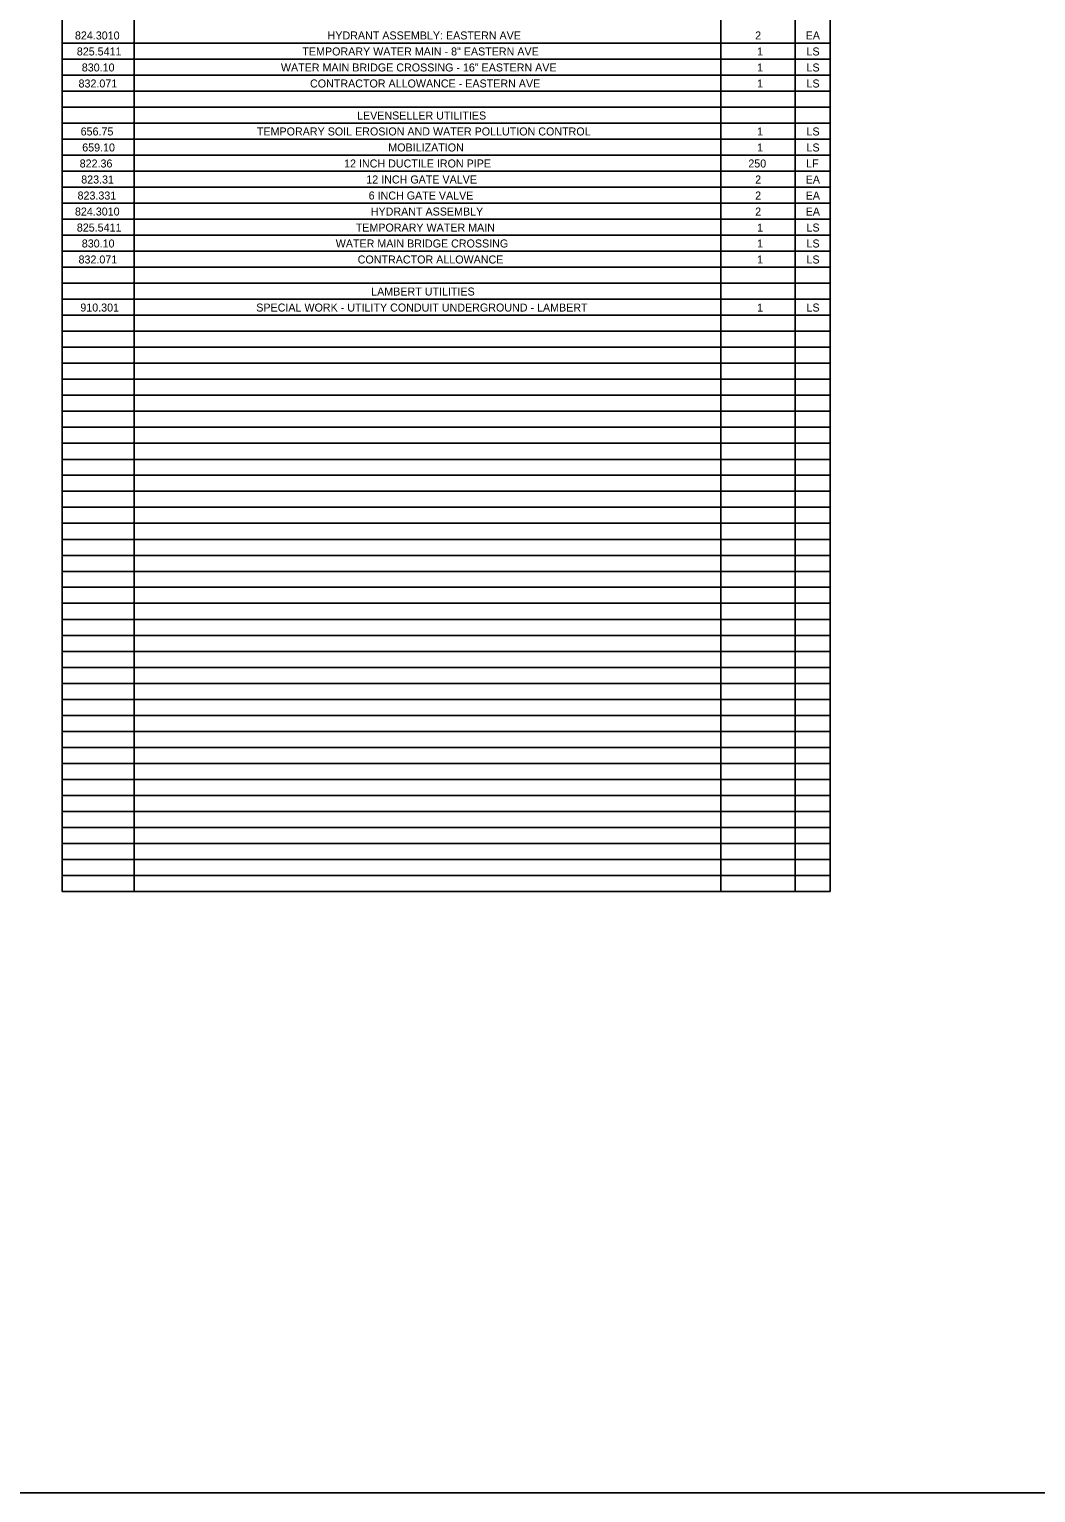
# Model space of a CAD drawing. Extents: x -18.7 to 5.6, y -2.7 to 5.1.
# Drawn here: x -5.226 to -3.989, y 1.503 to 3.303 of the extents above; entities that cross this region are included whole.
import ezdxf

# ---------------------------------------------------------------- set-up
doc = ezdxf.new("R2010")
doc.units = 0
for name, color, linetype in [('ANNOTATION', 7, 'Continuous'), ('BORDER', 7, 'Continuous'), ('Default', 7, 'Continuous')]:
    doc.layers.add(name, color=color, linetype=linetype)

msp = doc.modelspace()

# ---------------------------------------------------------------- linework, layer by layer
at = {"layer": 'BORDER'}
for p, q in [((-5.0975, 3.9551), (-5.0975, 2.2424)), ((-4.3761, 3.9551), (-4.3761, 2.2424)), ((-4.2848, 3.9551), (-4.2848, 2.2424)), ((-5.186, 3.2858), (-4.2418, 3.2858)), ((-5.186, 3.2661), (-4.2418, 3.2661)), ((-5.186, 3.2464), (-4.2418, 3.2464)), ((-5.186, 3.2267), (-4.2418, 3.2267)), ((-5.186, 3.207), (-4.2418, 3.207)), ((-5.186, 3.1873), (-4.2418, 3.1873)), ((-5.186, 3.1677), (-4.2418, 3.1677)), ((-5.186, 3.148), (-4.2418, 3.148)), ((-5.186, 3.1283), (-4.2418, 3.1283)), ((-5.186, 3.1086), (-4.2418, 3.1086)), ((-5.186, 3.0889), (-4.2418, 3.0889)), ((-5.186, 3.0692), (-4.2418, 3.0692)), ((-5.186, 3.0495), (-4.2418, 3.0495)), ((-5.186, 3.0299), (-4.2418, 3.0299)), ((-5.186, 3.0102), (-4.2418, 3.0102)), ((-5.186, 2.9905), (-4.2418, 2.9905)), ((-5.186, 2.9708), (-4.2418, 2.9708)), ((-5.186, 2.9511), (-4.2418, 2.9511)), ((-5.186, 2.9314), (-4.2418, 2.9314)), ((-5.186, 2.9117), (-4.2418, 2.9117)), ((-5.186, 2.8921), (-4.2418, 2.8921)), ((-5.186, 2.8724), (-4.2418, 2.8724)), ((-5.186, 2.8527), (-4.2418, 2.8527)), ((-5.186, 2.833), (-4.2418, 2.833)), ((-5.186, 2.8133), (-4.2418, 2.8133)), ((-5.186, 2.7936), (-4.2418, 2.7936)), ((-5.186, 2.7739), (-4.2418, 2.7739)), ((-5.186, 2.7543), (-4.2418, 2.7543)), ((-5.186, 2.7346), (-4.2418, 2.7346)), ((-5.186, 2.7149), (-4.2418, 2.7149)), ((-5.186, 2.6952), (-4.2418, 2.6952)), ((-5.186, 2.6755), (-4.2418, 2.6755)), ((-5.186, 2.6558), (-4.2418, 2.6558)), ((-5.186, 2.6361), (-4.2418, 2.6361)), ((-5.186, 2.6165), (-4.2418, 2.6165)), ((-5.186, 2.5968), (-4.2418, 2.5968)), ((-5.186, 2.5771), (-4.2418, 2.5771)), ((-5.186, 2.5574), (-4.2418, 2.5574)), ((-5.186, 2.5377), (-4.2418, 2.5377)), ((-5.186, 2.518), (-4.2418, 2.518)), ((-5.186, 2.4983), (-4.2418, 2.4983)), ((-5.186, 2.4787), (-4.2418, 2.4787)), ((-5.186, 2.459), (-4.2418, 2.459)), ((-5.186, 2.4393), (-4.2418, 2.4393)), ((-5.186, 2.4196), (-4.2418, 2.4196)), ((-5.186, 2.3999), (-4.2418, 2.3999)), ((-5.186, 2.3802), (-4.2418, 2.3802)), ((-5.186, 2.3605), (-4.2418, 2.3605)), ((-5.186, 2.3408), (-4.2418, 2.3408)), ((-5.186, 2.3212), (-4.2418, 2.3212)), ((-5.186, 2.3015), (-4.2418, 2.3015)), ((-5.186, 2.2818), (-4.2418, 2.2818)), ((-5.186, 2.2621), (-4.2418, 2.2621)), ((-5.186, 2.2424), (-4.2418, 2.2424))]:
    msp.add_line(p, q, dxfattribs=at)
msp.add_lwpolyline([(-5.186, 3.9748), (-4.2418, 3.9748), (-4.2418, 2.2424), (-5.186, 2.2424)], close=True, dxfattribs=at)
at = {"layer": 'Default'}
msp.add_lwpolyline([(-10.8151, 5.0978), (-2.7516, 5.0978), (-2.7516, 1.5028), (-10.8151, 1.5028)], close=True, dxfattribs=at)

# ---------------------------------------------------------------- texts
at = {"layer": 'ANNOTATION'}
for s, height, p in [('824.3010', 0.00984, (-5.1702, 3.2904)), ('HYDRANT ASSEMBLY: EASTERN AVE', 0.009843, (-4.8596, 3.2904)), ('2', 0.00984, (-4.3339, 3.2904)), ('EA', 0.00984, (-4.2718, 3.2904)), ('825.5411', 0.00984, (-5.1679, 3.2707)), ('TEMPORARY WATER MAIN - 8" EASTERN AVE', 0.009843, (-4.8906, 3.2707)), ('1', 0.00984, (-4.3315, 3.2707)), ('LS', 0.00984, (-4.2708, 3.2707)), ('830.10', 0.00984, (-5.1618, 3.251)), ('WATER MAIN BRIDGE CROSSING - 16" EASTERN AVE', 0.009843, (-4.917, 3.251)), ('1', 0.00984, (-4.3315, 3.251)), ('LS', 0.00984, (-4.2708, 3.251)), ('832.071', 0.00984, (-5.1658, 3.2313)), ('CONTRACTOR ALLOWANCE - EASTERN AVE', 0.009843, (-4.8812, 3.2313)), ('1', 0.00984, (-4.3315, 3.2313)), ('LS', 0.00984, (-4.2708, 3.2313)), ('LEVENSELLER UTILITIES', 0.009843, (-4.8234, 3.1919)), ('656.75', 0.00984, (-5.1632, 3.1723)), ('TEMPORARY SOIL EROSION AND WATER POLLUTION CONTROL', 0.009843, (-4.9465, 3.1723)), ('1', 0.00984, (-4.3315, 3.1723)), ('LS', 0.00984, (-4.2708, 3.1723)), ('659.10', 0.00984, (-5.1613, 3.1526)), ('MOBILIZATION', 0.009843, (-4.785, 3.1526)), ('1', 0.00984, (-4.3315, 3.1526)), ('LS', 0.00984, (-4.2708, 3.1526)), ('822.36', 0.00984, (-5.1644, 3.1329)), ('12 INCH DUCTILE IRON PIPE', 0.009843, (-4.8393, 3.1329)), ('250', 0.00984, (-4.3423, 3.1329)), ('LF', 0.00984, (-4.2712, 3.1329)), ('823.31', 0.00984, (-5.1625, 3.1132)), ('12 INCH GATE VALVE', 0.009843, (-4.812, 3.1132)), ('2', 0.00984, (-4.3339, 3.1132)), ('EA', 0.00984, (-4.2718, 3.1132)), ('823.331', 0.00984, (-5.167, 3.0935)), ('6 INCH GATE VALVE', 0.009843, (-4.8091, 3.0935)), ('2', 0.00984, (-4.3339, 3.0935)), ('EA', 0.00984, (-4.2718, 3.0935)), ('824.3010', 0.00984, (-5.1702, 3.0738)), ('HYDRANT ASSEMBLY', 0.009843, (-4.8065, 3.0738)), ('2', 0.00984, (-4.3339, 3.0738)), ('EA', 0.00984, (-4.2718, 3.0738)), ('825.5411', 0.00984, (-5.1679, 3.0541)), ('TEMPORARY WATER MAIN', 0.009843, (-4.825, 3.0541)), ('1', 0.00984, (-4.3315, 3.0541)), ('LS', 0.00984, (-4.2708, 3.0541)), ('830.10', 0.00984, (-5.1618, 3.0345)), ('WATER MAIN BRIDGE CROSSING', 0.009843, (-4.8496, 3.0345)), ('1', 0.00984, (-4.3315, 3.0345)), ('LS', 0.00984, (-4.2708, 3.0345)), ('832.071', 0.00984, (-5.1658, 3.0148)), ('CONTRACTOR ALLOWANCE', 0.009843, (-4.8226, 3.0148)), ('1', 0.00984, (-4.3315, 3.0148)), ('LS', 0.00984, (-4.2708, 3.0148)), ('LAMBERT UTILITIES', 0.009843, (-4.806, 2.9754)), ('910.301', 0.00984, (-5.1636, 2.9557)), ('SPECIAL WORK - UTILITY CONDUIT UNDERGROUND - LAMBERT', 0.009843, (-4.9473, 2.9557)), ('1', 0.00984, (-4.3315, 2.9557)), ('LS', 0.00984, (-4.2708, 2.9557))]:
    msp.add_text(s, height=height, dxfattribs=at).set_placement(p)

doc.saveas('drawing.dxf')
